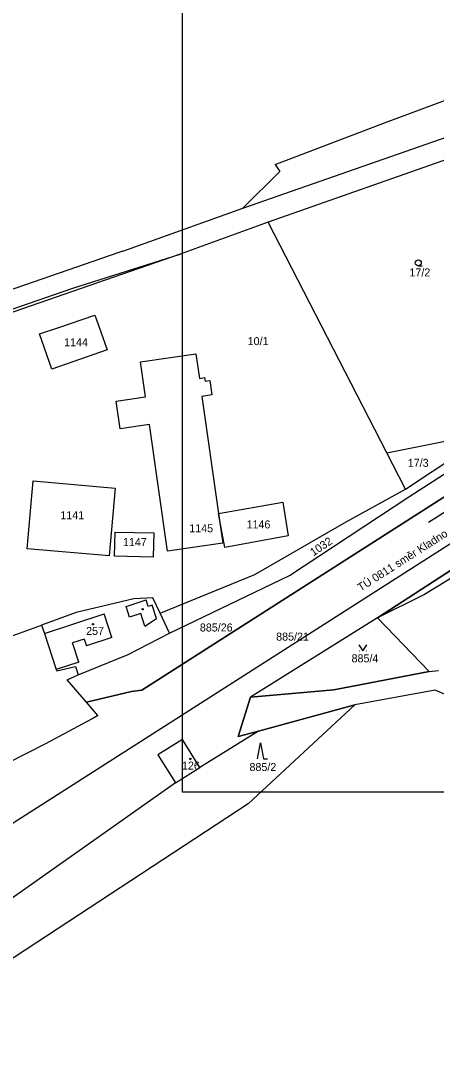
# Model space of a CAD drawing. Extents: x -752184 to -751416, y -1028299 to -1027836.
# Drawn here: x -751921.2 to -751817.4, y -1028255.6 to -1027995.9 of the extents above; entities that cross this region are included whole.
import ezdxf

# ---------------------------------------------------------------- set-up
doc = ezdxf.new("R2010")
doc.units = 0
for name, color, linetype in [('02_Osa_koleje', 7, 'Continuous'), ('Vrstva 4', 7, 'Continuous'), ('Vrstva 53', 7, 'Continuous'), ('Vrstva 55', 7, 'Continuous'), ('Vrstva 56', 7, 'Continuous'), ('Vrstva 57', 7, 'Continuous'), ('Vrstva 58', 7, 'Continuous'), ('Vrstva 59', 7, 'Continuous'), ('Vrstva 63', 7, 'Continuous')]:
    doc.layers.add(name, color=color, linetype=linetype)

msp = doc.modelspace()

# ---------------------------------------------------------------- linework, layer by layer
at = {"layer": '02_Osa_koleje'}
for p, q in [((-751818.04, -1028120.32), (-751810.27, -1028115.34)), ((-751819.33, -1028121.15), (-751818.04, -1028120.32))]:
    msp.add_line(p, q, dxfattribs=at)
at = {"layer": 'Vrstva 4'}
msp.add_lwpolyline([(-751880.79, -1027897.6), (-751466.79, -1027897.6), (-751466.79, -1028188.6), (-751880.79, -1028188.6)], close=True, dxfattribs=at)
at = {"layer": 'Vrstva 53'}
for points in [[(-751934.1, -1028186.19), (-751914.9, -1028176.41), (-751903.43, -1028170.23), (-751901.96, -1028169.44), (-751904.77, -1028166.14), (-751893.52, -1028163.47), (-751890.97, -1028163.13), (-751806.75, -1028109.29), (-751808.53, -1028106.05), (-751798.29, -1028099.68), (-751750.57, -1028069.21), (-751709.61, -1028036.63), (-751702.85, -1028029.39), (-751690.7, -1028035.11), (-751634.83, -1027999.42), (-751532.07, -1027933.64), (-751519.82, -1027926.47), (-751506.87, -1027919.58), (-751494.13, -1027913.25), (-751481.54, -1027906.54), (-751469.19, -1027899.14), (-751466.79, -1027897.6)], [(-751644.14, -1028025.2), (-751657.66, -1028033.82), (-751657.93, -1028033.4), (-751685.36, -1028050.92), (-751685.1, -1028051.35), (-751700.15, -1028061), (-751700.39, -1028060.59), (-751811.98, -1028131.93), (-751832.08, -1028145), (-751819.17, -1028158.43), (-751842.96, -1028162.99), (-751863.83, -1028164.81), (-751866.87, -1028174.68), (-751861.84, -1028173.32), (-751837.73, -1028166.78), (-751864.36, -1028191.47), (-751928.16, -1028233.3)]]:
    msp.add_lwpolyline(points, dxfattribs=at)
at = {"layer": 'Vrstva 55'}
for p, q in [((-751830.33, -1028021.31), (-751777.61, -1028001.77)), ((-751857.65, -1028031.73), (-751830.33, -1028021.31)), ((-751803.99, -1028026.65), (-751859.41, -1028046.14)), ((-751895.64, -1028053.38), (-751865.7, -1028042.71)), ((-751859.41, -1028046.14), (-751881.38, -1028054.14)), ((-751829.79, -1028103.79), (-751859.41, -1028046.14)), ((-751896.64, -1028053.77), (-751913.74, -1028059.67)), ((-751895.64, -1028053.38), (-751896.64, -1028053.77)), ((-751881.38, -1028054.14), (-752003.38, -1028096.4)), ((-751913.74, -1028059.67), (-751933.45, -1028066.43)), ((-751825.11, -1028112.91), (-751790.46, -1028089.89)), ((-751825.11, -1028112.91), (-751829.79, -1028103.79)), ((-751832.08, -1028145), (-751811.98, -1028131.93)), ((-751884.03, -1028148.84), (-751886.38, -1028143.87)), ((-751832.08, -1028145), (-751863.83, -1028164.81)), ((-751832.08, -1028145), (-751819.17, -1028158.43)), ((-751909.62, -1028160.48), (-751906.85, -1028159.28)), ((-751819.17, -1028158.43), (-751816.81, -1028158.16)), ((-751904.77, -1028166.14), (-751909.62, -1028160.48)), ((-751893.52, -1028163.47), (-751904.77, -1028166.14)), ((-751901.96, -1028169.44), (-751904.77, -1028166.14)), ((-751837.73, -1028166.78), (-751861.84, -1028173.32)), ((-751901.96, -1028169.44), (-751903.43, -1028170.23)), ((-751861.84, -1028173.32), (-751876.44, -1028182.41)), ((-751882.55, -1028186.22), (-751876.44, -1028182.41)), ((-751882.55, -1028186.22), (-751980.73, -1028255.56))]:
    msp.add_line(p, q, dxfattribs=at)
for points in [[(-751865.7, -1028042.71), (-751749.56, -1028002.08), (-751713.49, -1027990.7), (-751668.79, -1027968.97)], [(-751857.65, -1028031.73), (-751856.49, -1028033.54), (-751865.7, -1028042.71)], [(-752003.56, -1028095.62), (-751908.15, -1028062.63), (-751881.38, -1028054.14)], [(-751698.4, -1028064.61), (-751729.61, -1028083.77), (-751749, -1028095.68), (-751820.32, -1028139.23), (-751832.08, -1028145)], [(-751902.66, -1028069.39), (-751901.2, -1028073.54), (-751899.62, -1028078.07), (-751913.4, -1028082.89), (-751916.47, -1028074.11), (-751911.88, -1028072.54), (-751902.66, -1028069.39)], [(-751750.57, -1028069.21), (-751798.29, -1028099.68), (-751808.53, -1028106.05), (-751806.75, -1028109.29), (-751890.97, -1028163.13), (-751893.52, -1028163.47)], [(-751884.03, -1028148.84), (-751854.09, -1028134.41), (-751824.25, -1028114.78), (-751751.51, -1028067.92)], [(-751871.76, -1028119), (-751870.71, -1028126.36), (-751884.51, -1028128.34), (-751889.05, -1028096.75), (-751896.33, -1028097.8), (-751897.36, -1028090.88), (-751890.04, -1028089.83), (-751891.29, -1028081.06), (-751877.43, -1028079.08), (-751876.57, -1028085.19), (-751875.28, -1028085.01), (-751875.15, -1028085.9), (-751873.96, -1028085.73), (-751873.45, -1028089.34), (-751875.93, -1028089.7), (-751871.76, -1028119)], [(-751829.79, -1028103.79), (-751815.64, -1028100.96), (-751805.78, -1028097.41), (-751790.88, -1028089.26), (-751790.46, -1028089.89)], [(-751897.63, -1028112.6), (-751899.12, -1028129.53), (-751919.55, -1028127.76), (-751918.08, -1028110.8), (-751897.63, -1028112.6)], [(-751886.38, -1028143.87), (-751862.7, -1028134.19), (-751839.92, -1028121.01), (-751825.11, -1028112.91)], [(-751871.76, -1028119), (-751855.74, -1028116.09), (-751854.37, -1028124.51), (-751870.23, -1028127.46), (-751871.76, -1028119)], [(-751897.58, -1028123.64), (-751887.96, -1028123.82), (-751888.1, -1028129.87), (-751897.72, -1028129.64), (-751897.58, -1028123.64)], [(-751886.38, -1028143.87), (-751888.21, -1028140.02), (-751892.91, -1028140.3), (-751907.34, -1028143.68), (-751915.97, -1028146.83)], [(-751948.62, -1028160.91), (-751948.85, -1028157.62), (-751925.12, -1028150.18), (-751915.97, -1028146.83)], [(-751915.97, -1028146.83), (-751915.28, -1028148.92), (-751912.32, -1028157.92), (-751912.2, -1028158.29)], [(-751906.85, -1028159.28), (-751894.37, -1028154.17), (-751884.03, -1028148.84)], [(-751912.2, -1028158.29), (-751907.54, -1028157.19), (-751906.85, -1028159.28)], [(-751863.83, -1028164.81), (-751842.96, -1028162.99), (-751819.17, -1028158.43)], [(-751861.84, -1028173.32), (-751866.87, -1028174.68), (-751863.83, -1028164.81)], [(-751742.53, -1028181.08), (-751751.04, -1028178.81), (-751790.89, -1028174.07), (-751809.18, -1028166.74), (-751817.68, -1028163.14), (-751837.73, -1028166.78)], [(-751837.73, -1028166.78), (-751864.36, -1028191.47), (-751928.16, -1028233.3), (-751967.27, -1028248.1), (-751980.73, -1028255.56)], [(-752025.93, -1028240.15), (-751982.6, -1028213.59), (-751934.1, -1028186.19), (-751914.9, -1028176.41), (-751903.43, -1028170.23)], [(-751876.44, -1028182.41), (-751880.8, -1028175.41), (-751886.93, -1028179.3), (-751882.55, -1028186.22)]]:
    msp.add_lwpolyline(points, dxfattribs=at)
at = {"layer": 'Vrstva 56'}
for p, q in [((-751894.85, -1028142.2), (-751889.87, -1028140.56)), ((-751889.34, -1028142.18), (-751889.87, -1028140.56)), ((-751888.34, -1028141.85), (-751889.34, -1028142.18)), ((-751887.25, -1028145.18), (-751888.34, -1028141.85)), ((-751915.28, -1028148.92), (-751900.38, -1028144.02)), ((-751898.43, -1028149.96), (-751900.38, -1028144.02)), ((-751893.98, -1028144.86), (-751894.85, -1028142.2)), ((-751891.22, -1028143.96), (-751893.98, -1028144.86)), ((-751890.18, -1028147.14), (-751891.22, -1028143.96)), ((-751890.18, -1028147.14), (-751887.25, -1028145.18)), ((-751905.3, -1028150.34), (-751908.27, -1028151.31)), ((-751906.7, -1028156.07), (-751908.27, -1028151.31)), ((-751905.3, -1028150.34), (-751904.74, -1028152.04)), ((-751898.43, -1028149.96), (-751904.74, -1028152.04)), ((-751906.7, -1028156.07), (-751912.32, -1028157.92))]:
    msp.add_line(p, q, dxfattribs=at)
at = {"layer": 'Vrstva 58'}
for p, q in [((-751821.89, -1028057.08), (-751820.89, -1028057.08)), ((-751836.66, -1028153.26), (-751836.56, -1028153.26)), ((-751834.86, -1028153.26), (-751834.76, -1028153.26))]:
    msp.add_line(p, q, dxfattribs=at)
for points in [[(-751836.71, -1028151.76), (-751835.71, -1028153.26), (-751834.71, -1028151.76)], [(-751862.07, -1028180.28), (-751861.32, -1028176.28), (-751860.57, -1028180.28), (-751859.57, -1028180.28)]]:
    msp.add_lwpolyline(points, dxfattribs=at)
msp.add_circle((-751821.89, -1028056.33), 0.75, dxfattribs=at)
at = {"layer": 'Vrstva 59'}
for centre in [(-751890.74, -1028142.88), (-751903.15, -1028146.63), (-751878.83, -1028180.29)]:
    msp.add_circle(centre, 0.175, dxfattribs=at)
at = {"layer": 'Vrstva 63'}
msp.add_line((-751551.77, -1027958.95), (-751975.84, -1028230), dxfattribs=at)

# ---------------------------------------------------------------- texts
at = {"layer": '02_Osa_koleje'}
msp.add_text('TÚ 0811 směr Kladno', height=2, rotation=32.6028, dxfattribs=at).set_placement((-751836.27, -1028138.5))
at = {"layer": 'Vrstva 57'}
for s, p in [('17/2', (-751824.11, -1028059.72)), ('1144', (-751910.34, -1028077.17)), ('10/1', (-751864.51, -1028076.89)), ('17/3', (-751824.52, -1028107.3)), ('1141', (-751911.28, -1028120.38)), ('1146', (-751864.79, -1028122.68)), ('1145', (-751879.09, -1028123.65)), ('1147', (-751895.65, -1028127.09)), ('257', (-751904.85, -1028149.31)), ('885/26', (-751876.44, -1028148.44)), ('885/21', (-751857.39, -1028150.72)), ('885/4', (-751838.56, -1028156.15)), ('126', (-751880.91, -1028182.95)), ('885/2', (-751864.05, -1028183.3))]:
    msp.add_text(s, height=2, dxfattribs=at).set_placement(p)
msp.add_text('1032', height=2, rotation=34, dxfattribs=at).set_placement((-751848.08, -1028129.69))

doc.saveas('drawing.dxf')
